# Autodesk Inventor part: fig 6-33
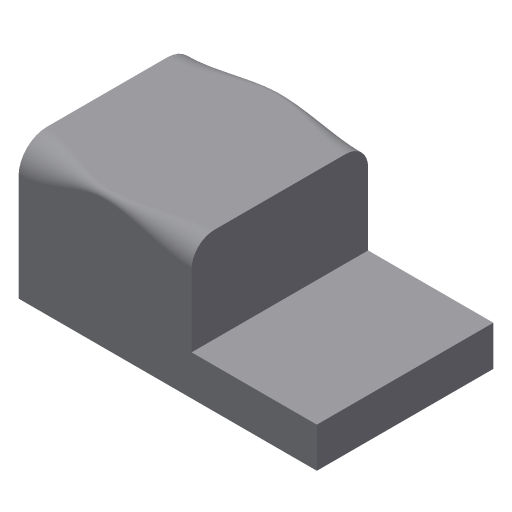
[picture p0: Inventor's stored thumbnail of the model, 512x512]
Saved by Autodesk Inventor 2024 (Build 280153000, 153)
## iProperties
Created: 2004-05
Part Number: fig 6-33
Document SubType Name: Modeling
Designer: CADCIM Technologies
Manufacturer: Standard
Standards Organization: Custom
Density: 1 g/cm^3
Material: Generic
Appearance: Default
Author: CADCIM Technologies
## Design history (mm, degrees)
sketch "Sketch2"
  geometry: L1 (0.098, 47.711)-(0.098, 0.049); L2 (0.098, 0.049)-(-105.483, 0.049); L3 (-105.483, 0.049)-(-105.483, 14.192); L4 (-105.483, 14.192)-(-61.139, 14.192); L5 (-61.139, 14.192)-(-61.139, 47.711); L6 (-61.139, 47.711)-(0.098, 47.711)
  constraints: 12 end point, 3 parallel, 2 perpendicular, 1 vertical
extrude "Extrusion1" new body sketch "Sketch2" stored distance "d0" = 62.5; taper "d1" = 0 deg
fillet "Fillet9" dims "d61" = 10, "d62" = 8, "d63" = 2, "d64" = 5
fillet "Fillet10" dims "d65" = 8, "d66" = 10, "d67" = 2, "d68" = 5
body "Solid1"
node "Sketch1"
